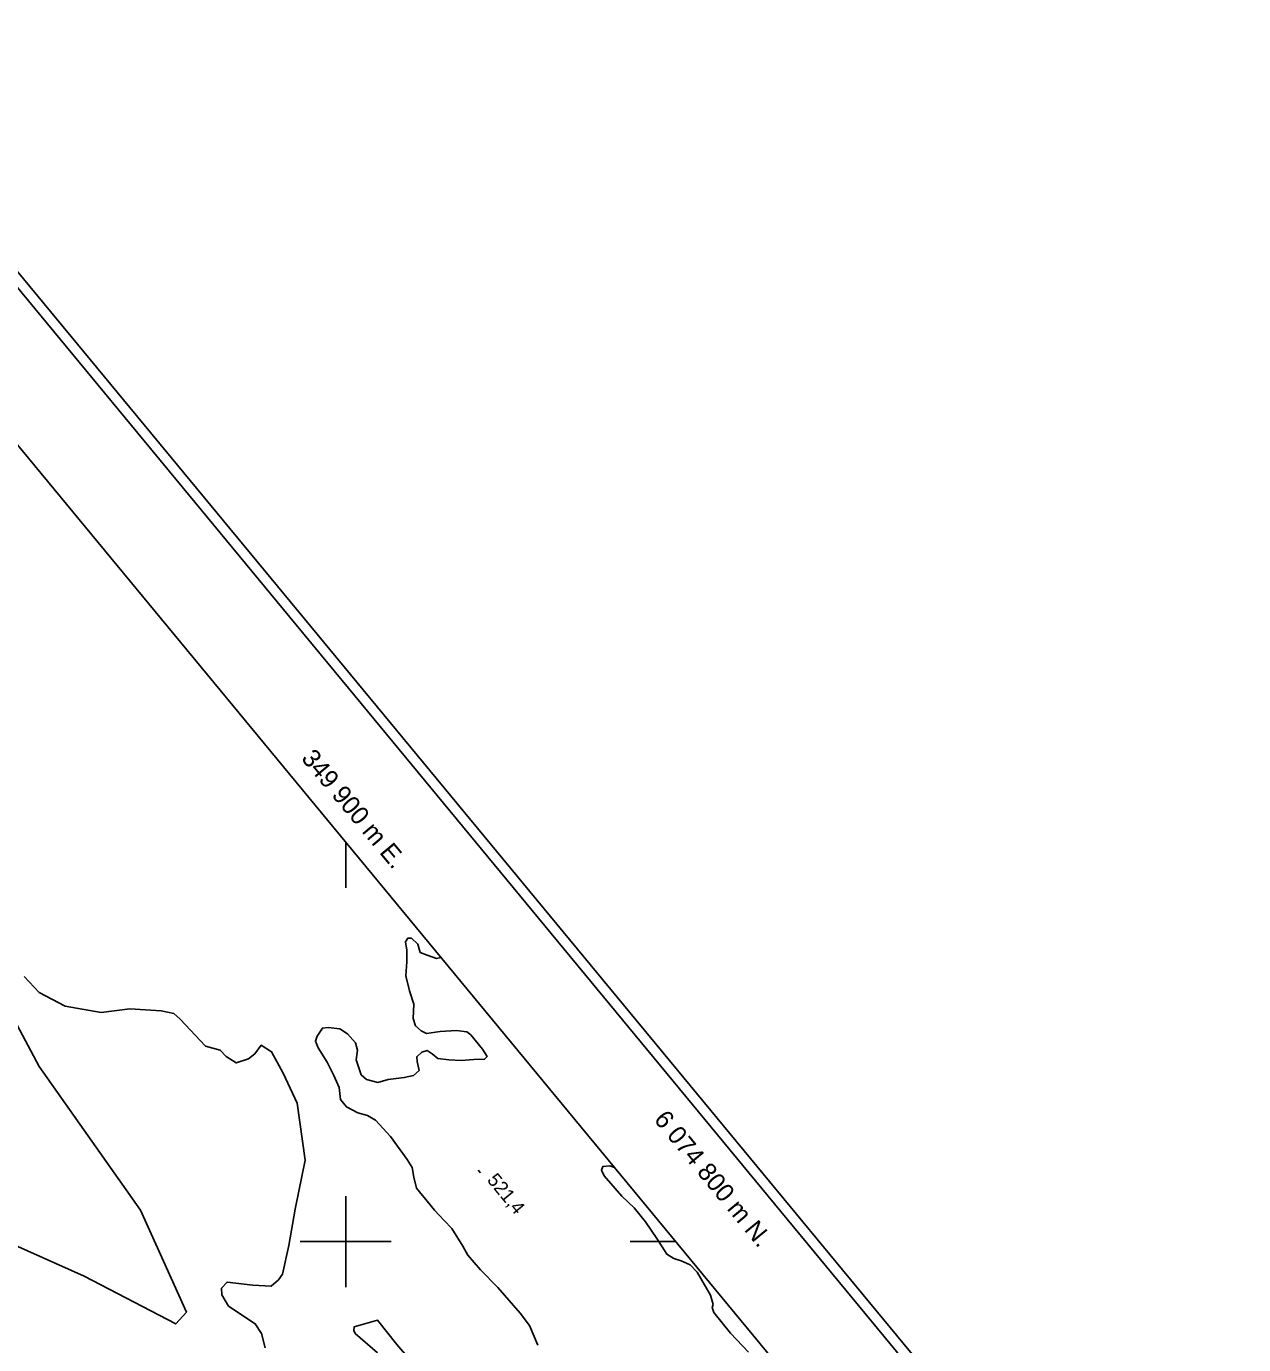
# Model space of a CAD drawing. Extents: x 347312 to 350503, y 6073086 to 6076432.
# Drawn here: x 349830 to 350096.8, y 6074777.4 to 6075066.4 of the extents above; entities that cross this region are included whole.
import ezdxf

# ---------------------------------------------------------------- set-up
doc = ezdxf.new("R2010")
doc.units = 0
for name, color, linetype in [('Level 1', 7, 'Continuous'), ('Level 2', 7, 'Continuous'), ('Level 3', 7, 'Continuous'), ('Level 44', 7, 'Continuous'), ('Level 60', 7, 'Continuous'), ('Level 61', 7, 'Continuous')]:
    doc.layers.add(name, color=color, linetype=linetype)

msp = doc.modelspace()

# ---------------------------------------------------------------- linework, layer by layer
at = {"layer": 'Level 1'}
for points in [[(349922.63, 6074839.86), (349925.34, 6074839.68), (349928.08, 6074839.93), (349930.45, 6074839.99), (349930.99, 6074840.6), (349930.02, 6074842.18), (349927.43, 6074845.31), (349926.55, 6074846.01), (349924.27, 6074846.31), (349920.74, 6074846.04), (349917.7, 6074845.66), (349916.52, 6074846.25), (349915.31, 6074847.34), (349914.76, 6074848.89), (349914.97, 6074852.04), (349914.02, 6074854.99), (349913.16, 6074858.29), (349913.43, 6074861.37), (349913.38, 6074863.9), (349913.14, 6074865.71), (349913.63, 6074866.55), (349914.42, 6074866.57), (349915.84, 6074865.25), (349916.36, 6074863.41), (349917.83, 6074862.81), (349919.93, 6074862.09), (349920.86, 6074862.32)], [(349942.09, 6074777.28), (349940.3, 6074781.64), (349938.25, 6074784.3), (349933.32, 6074789.95), (349929.56, 6074793.8), (349926.76, 6074797.01), (349925.68, 6074799.03), (349923.28, 6074802.86), (349921.6, 6074804.63), (349919.46, 6074806.93), (349917.87, 6074808.91), (349915.54, 6074811.73), (349914.92, 6074814.15), (349914.55, 6074816.26), (349913.45, 6074817.99), (349909.84, 6074823.06), (349906.56, 6074826.66), (349904.76, 6074827.64), (349902.65, 6074828.22), (349900.15, 6074829.53), (349898.89, 6074831.13), (349898.57, 6074833.82), (349897.38, 6074836.42), (349895.92, 6074839.33), (349893.97, 6074842.48), (349893.35, 6074843.97), (349893.78, 6074845.02), (349894.9, 6074846.82), (349896.13, 6074846.95), (349898.69, 6074846.64), (349900.42, 6074845.59), (349902.15, 6074843.6), (349902.62, 6074841.98), (349902.33, 6074839.84), (349903.41, 6074836.6), (349904.57, 6074835.58), (349907.03, 6074834.92), (349909.3, 6074835.56), (349912.84, 6074835.97), (349914.87, 6074836.41), (349916.09, 6074837.49), (349915.65, 6074839.53), (349915.58, 6074840.55), (349916.72, 6074841.55), (349917.89, 6074841.91), (349918.92, 6074841.19), (349920.21, 6074840.17), (349922.63, 6074839.86)], [(349958.9, 6074816.28), (349957.93, 6074816.63), (349956.34, 6074816.45), (349956.08, 6074815.68), (349956.64, 6074814.41), (349960.5, 6074809.98), (349963.27, 6074807.42), (349965.71, 6074804.31)], [(349965.71, 6074804.31), (349968.2, 6074800.69), (349970.4, 6074797.23), (349971.91, 6074796.27), (349973.53, 6074795.8), (349975.48, 6074794.95), (349977.02, 6074793.34), (349979.98, 6074788.25), (349980.56, 6074786.2), (349980.3, 6074785.57), (349980.73, 6074784.46), (349984.37, 6074779.97), (349988.32, 6074775.75)]]:
    msp.add_lwpolyline(points, dxfattribs=at)
at = {"layer": 'Level 2'}
for points in [[(349829.53, 6074858.1), (349832.82, 6074854.61)], [(349832.82, 6074854.61), (349838.51, 6074851.65), (349846.4, 6074850.24), (349852.68, 6074851.03), (349859.53, 6074850.6), (349862.32, 6074850.04), (349863.74, 6074848.78), (349869.27, 6074842.87), (349872.47, 6074841.99), (349873.8, 6074840.58), (349876.02, 6074839.17), (349878.69, 6074840.07), (349880.05, 6074841.21), (349881.48, 6074843.07), (349883.74, 6074841.62), (349886.3, 6074836.94), (349889.33, 6074830.36), (349891.12, 6074817.86), (349888.9, 6074807.13), (349887.54, 6074799.12), (349886.11, 6074792.89), (349885.3, 6074791.63), (349883.64, 6074790.23), (349879.65, 6074790.45), (349874.01, 6074791.14), (349872.8, 6074789.83), (349872.82, 6074788.37), (349874.33, 6074785.86), (349880.16, 6074782), (349881.53, 6074779.83), (349882.34, 6074776.73)], [(349906.94, 6074775.63), (349902.04, 6074779.88), (349901.78, 6074780.55), (349901.82, 6074781.32), (349906.97, 6074782.82), (349911.2, 6074777.48), (349916.59, 6074771.13)]]:
    msp.add_lwpolyline(points, dxfattribs=at)
at = {"layer": 'Level 3'}
msp.add_line((349929.03, 6074815.68), (349929.54, 6074815.06), dxfattribs=at)
at = {"layer": 'Level 44'}
msp.add_lwpolyline([(349821.21, 6074802.02), (349842.68, 6074792.41), (349862.75, 6074781.96), (349865.09, 6074784.51), (349855.03, 6074806.88), (349832.83, 6074838.42), (349823.69, 6074855.42)], dxfattribs=at)
at = {"layer": 'Level 60'}
for p, q in [((349900, 6074887.57), (349900, 6074877.57)), ((349962.36, 6074800), (349972.36, 6074800))]:
    msp.add_line(p, q, dxfattribs=at)
msp.add_lwpolyline([(350502.67, 6074196.28), (348655.35, 6076431.86)], dxfattribs=at)
for points in [[(349159.76, 6073089.49), (347315.28, 6075321.63), (348655.04, 6076428.72), (350499.52, 6074196.58)], [(348779.44, 6073584.28), (350085.28, 6074663.34), (348652.09, 6076397.74), (347346.25, 6075318.68)]]:
    msp.add_lwpolyline(points, close=True, dxfattribs=at)
at = {"layer": 'Level 61'}
for p, q in [((349900, 6074810), (349900, 6074790)), ((349890, 6074800), (349910, 6074800))]:
    msp.add_line(p, q, dxfattribs=at)

# ---------------------------------------------------------------- texts
at = {"layer": 'Level 3'}
msp.add_text('521,4', height=3, rotation=309.5679, dxfattribs=at).set_placement((349930.84, 6074813.44))
at = {"layer": 'Level 61'}
for s, rotation, p in [('349 900 m E. ', 309.813, (349890.09, 6074905.86)), ('6 074 800 m N.', 309.3644, (349967.39, 6074826.71))]:
    msp.add_text(s, height=4, rotation=rotation, dxfattribs=at).set_placement(p)

doc.saveas('drawing.dxf')
